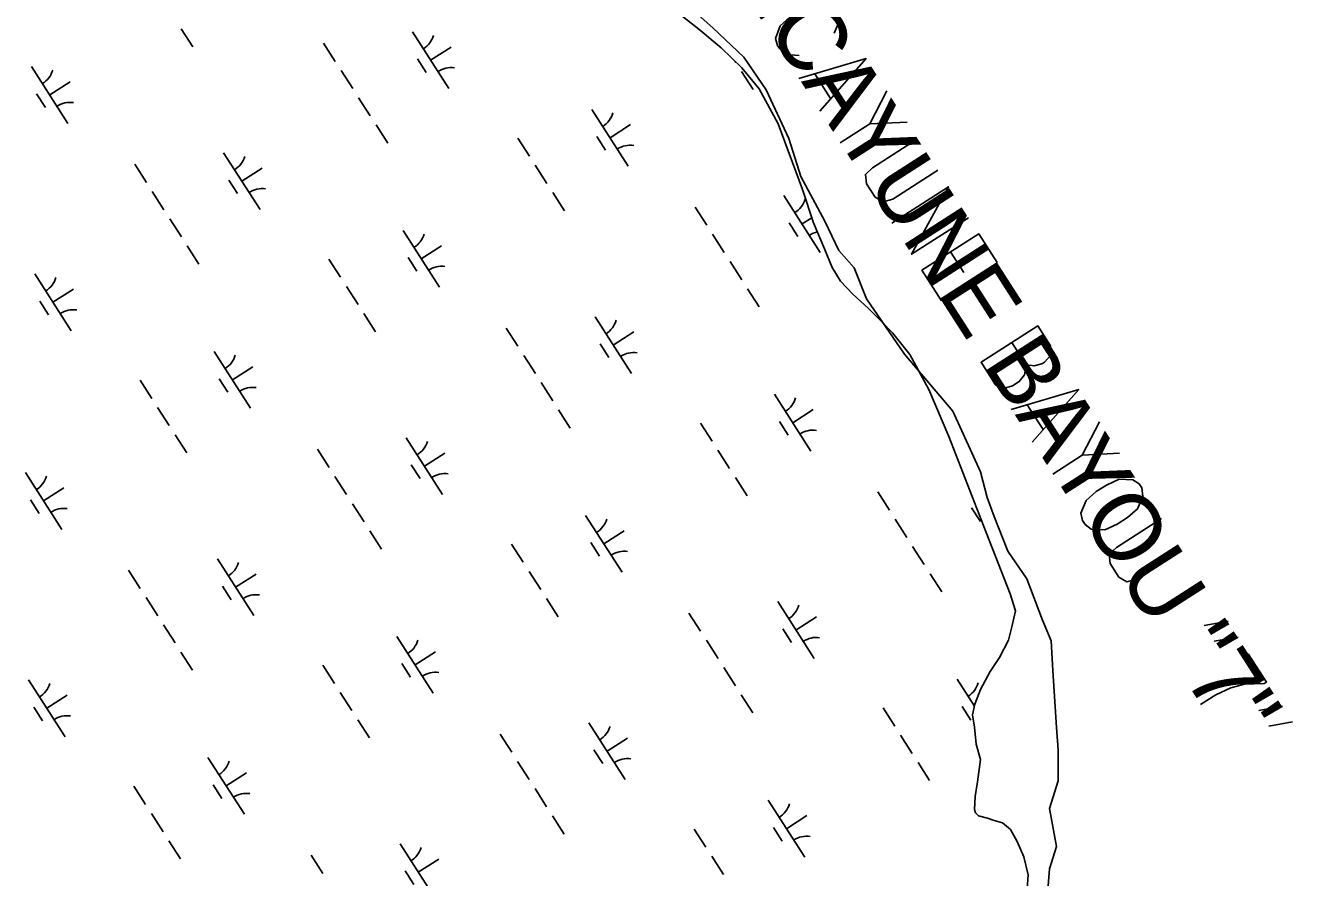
# Model space of a CAD drawing. Extents: x 3962991 to 3983549, y 181631 to 204078.
# Drawn here: x 3968183 to 3969123, y 196968 to 197600 of the extents above; entities that cross this region are included whole.
import ezdxf

# ---------------------------------------------------------------- set-up
doc = ezdxf.new("R2010")
doc.units = 0
for name, color, linetype in [('V-ANNO-MASK', 7, 'Continuous'), ('V-ANNO-MASK2', 7, 'Continuous'), ('V-CHAN-NAID', 7, 'Continuous'), ('V-RIVR-EDGE', 7, 'Continuous'), ('V-WETL-SWMP', 7, 'Continuous')]:
    doc.layers.add(name, color=color, linetype=linetype)

msp = doc.modelspace()

# ---------------------------------------------------------------- linework, layer by layer
at = {"layer": 'V-ANNO-MASK2'}
for p, q in [((3968780.21, 197545.37), (3968768.41, 197563.74)), ((3968809.17, 197526.5), (3968787.3, 197512.46)), ((3968869.15, 197431.61), (3968878.88, 197416.45)), ((3968937.81, 197299.89), (3968926.02, 197318.26)), ((3968966.77, 197281.02), (3968944.91, 197266.98)), ((3969057.26, 197154.66), (3969074.91, 197157.77)), ((3969064.74, 197143), (3969082.4, 197146.11)), ((3969097.69, 197091.69), (3969115.35, 197094.79)), ((3969105.18, 197080.03), (3969122.83, 197083.13))]:
    msp.add_line(p, q, dxfattribs=at)
for points in [[(3968782.72, 197593.92), (3968786.68, 197603.05), (3968785.01, 197608.57), (3968782.95, 197611.77), (3968778.82, 197615.29), (3968768.68, 197615.78), (3968758.66, 197610.99), (3968753.69, 197607.8), (3968750.37, 197605.68), (3968747.58, 197603.47), (3968742.84, 197599.19), (3968739.4, 197589.98), (3968740.88, 197584.76), (3968742.56, 197582.13), (3968747.07, 197578.03), (3968756.88, 197577.33)], [(3968756.6, 197560.27), (3968806.54, 197575.04), (3968772.14, 197536.07)], [(3968821.89, 197551.13), (3968809.17, 197526.5), (3968836.86, 197527.81)], [(3968844.72, 197515.56), (3968811.26, 197494.08), (3968806.05, 197489.09), (3968806.77, 197482.14), (3968813.13, 197472.22), (3968819.15, 197468.68), (3968826.24, 197470.76), (3968859.7, 197492.24)], [(3968825.49, 197452.98), (3968867.56, 197480), (3968840.27, 197429.95), (3968882.35, 197456.97)], [(3968903.69, 197423.73), (3968890.02, 197445.01), (3968847.95, 197418), (3968862.55, 197395.26)], [(3968925.28, 197347.84), (3968931.31, 197347.18), (3968937.22, 197348.92), (3968938.87, 197349.98), (3968943.57, 197355.05), (3968943.37, 197361.92), (3968933.82, 197376.79), (3968891.75, 197349.78), (3968902.42, 197333.16), (3968908.39, 197330.41), (3968915.15, 197332.28), (3968920.12, 197335.47), (3968923.96, 197340.41), (3968925.28, 197347.84), (3968914.61, 197364.45)], [(3968914.21, 197314.79), (3968964.15, 197329.56), (3968929.75, 197290.6)], [(3968979.49, 197305.66), (3968966.77, 197281.02), (3968994.47, 197282.33)], [(3969009.07, 197259.59), (3969010.94, 197256.68), (3969011.8, 197250.23), (3969007.84, 197241.1), (3969000.31, 197234.62), (3968992.69, 197229.73), (3968983.66, 197225.57), (3968973.52, 197226.06), (3968968.87, 197229.66), (3968966.99, 197232.58), (3968965.84, 197238.02), (3968969.62, 197247.44), (3968977.15, 197253.92), (3968984.77, 197258.82), (3968994.13, 197263.18), (3969004.27, 197262.69), (3969009.07, 197259.59)], [(3969025.54, 197233.94), (3968992.08, 197212.45), (3968986.87, 197207.46), (3968987.58, 197200.51), (3968993.95, 197190.6), (3968999.97, 197187.05), (3969007.06, 197189.13), (3969040.52, 197210.61)], [(3969089.93, 197133.65), (3969103.41, 197112.66), (3969101.75, 197111.59), (3969087.03, 197111.2), (3969077.07, 197108.51), (3969065.86, 197103.37), (3969054.6, 197096.14)]]:
    msp.add_lwpolyline(points, dxfattribs=at)
at = {"layer": 'V-RIVR-EDGE'}
msp.add_lwpolyline([(3968670.98, 197617.02), (3968692.76, 197597.81), (3968715.81, 197576.04), (3968732.46, 197551.71), (3968749.1, 197515.85), (3968758.07, 197487.67), (3968776, 197454.38), (3968786.24, 197432.61), (3968797.77, 197419.8), (3968806.73, 197396.75), (3968834.91, 197355.77), (3968870.76, 197313.51), (3968878.45, 197296.86), (3968891.25, 197268.69), (3968896.38, 197249.48), (3968901.5, 197235.39), (3968911.74, 197209.78), (3968925.83, 197189.29), (3968937.36, 197158.55), (3968943.76, 197143.18), (3968945.04, 197121.41), (3968947.6, 197079.15), (3968948.88, 197062.5), (3968948.88, 197039.45), (3968942.48, 197018.96), (3968947.6, 196990.79), (3968942.48, 196974.14), (3968939.92, 196939.56)], dxfattribs=at)
at = {"layer": 'V-WETL-SWMP'}
for p, q in [((3968664.23, 197611.02), (3968682.53, 197596.72)), ((3968298.66, 197597.13), (3968307.29, 197583.66)), ((3968470.1, 197594.89), (3968497.09, 197552.79)), ((3968682.53, 197596.72), (3968699.01, 197583.01)), ((3968404.22, 197586.41), (3968412.86, 197572.94)), ((3968473.86, 197574.73), (3968480.34, 197564.63)), ((3968483.6, 197573.84), (3968498.75, 197583.56)), ((3968699.01, 197583.01), (3968714.29, 197568.08)), ((3968187.62, 197569.06), (3968214.61, 197526.97)), ((3968417.18, 197566.21), (3968425.81, 197552.74)), ((3968709.36, 197572.89), (3968709.84, 197572.15)), ((3968714.16, 197565.41), (3968722.8, 197551.94)), ((3968714.29, 197568.08), (3968727.16, 197552.52)), ((3968201.12, 197548.02), (3968216.27, 197557.73)), ((3968191.38, 197548.9), (3968197.86, 197538.8)), ((3968430.13, 197546), (3968438.76, 197532.53)), ((3968727.16, 197552.52), (3968741.37, 197526.69)), ((3968603.13, 197537.34), (3968630.11, 197495.25)), ((3968443.08, 197525.8), (3968451.72, 197512.33)), ((3968616.62, 197516.3), (3968631.77, 197526.01)), ((3968741.37, 197526.69), (3968759.46, 197477.95)), ((3968548.22, 197516.05), (3968556.86, 197502.58)), ((3968606.89, 197517.19), (3968613.36, 197507.08)), ((3968330.07, 197505.11), (3968357.06, 197463.02)), ((3968264.19, 197496.64), (3968272.83, 197483.17)), ((3968343.56, 197484.07), (3968358.72, 197493.78)), ((3968561.18, 197495.84), (3968569.81, 197482.37)), ((3968333.83, 197484.95), (3968340.31, 197474.85)), ((3968277.14, 197476.43), (3968285.78, 197462.96)), ((3968574.13, 197475.64), (3968582.76, 197462.17)), ((3968745.58, 197473.39), (3968772.56, 197431.3)), ((3968759.46, 197477.95), (3968767.61, 197453.26)), ((3968679.7, 197464.92), (3968688.33, 197451.45)), ((3968290.1, 197456.23), (3968298.73, 197442.76)), ((3968749.34, 197453.23), (3968755.81, 197443.13)), ((3968759.07, 197452.35), (3968766.37, 197457.02)), ((3968767.61, 197453.26), (3968775.69, 197434.02)), ((3968463.1, 197447.57), (3968490.08, 197405.48)), ((3968692.65, 197444.72), (3968701.28, 197431.25)), ((3968303.05, 197436.03), (3968311.69, 197422.56)), ((3968476.59, 197426.53), (3968491.74, 197436.24)), ((3968775.69, 197434.02), (3968781.29, 197420.18)), ((3968408.19, 197426.27), (3968416.83, 197412.81)), ((3968466.86, 197427.41), (3968473.33, 197417.31)), ((3968705.6, 197424.51), (3968714.24, 197411.04)), ((3968190.04, 197415.34), (3968217.03, 197373.25)), ((3968781.29, 197420.18), (3968787.45, 197409.98)), ((3968421.14, 197406.07), (3968429.78, 197392.6)), ((3968787.45, 197409.98), (3968796.63, 197400.41)), ((3968203.53, 197394.29), (3968218.69, 197404.01)), ((3968718.56, 197404.31), (3968727.19, 197390.84)), ((3968796.63, 197400.41), (3968808.24, 197389.67)), ((3968193.8, 197395.18), (3968200.28, 197385.08)), ((3968808.24, 197389.67), (3968818.02, 197380.11)), ((3968434.1, 197385.87), (3968442.73, 197372.4)), ((3968605.55, 197383.62), (3968632.53, 197341.53)), ((3968818.02, 197380.11), (3968825.98, 197371.74)), ((3968539.66, 197375.15), (3968548.3, 197361.68)), ((3968619.04, 197362.57), (3968634.19, 197372.29)), ((3968825.98, 197371.74), (3968838.85, 197355.57)), ((3968609.3, 197363.46), (3968615.78, 197353.36)), ((3968323.06, 197357.8), (3968350.05, 197315.71)), ((3968552.62, 197354.94), (3968561.25, 197341.47)), ((3968838.85, 197355.57), (3968853.06, 197329.75)), ((3968336.56, 197336.75), (3968351.71, 197346.47)), ((3968268.16, 197336.5), (3968276.79, 197323.03)), ((3968326.82, 197337.64), (3968333.3, 197327.54)), ((3968565.57, 197334.74), (3968574.21, 197321.27)), ((3968738.57, 197326.08), (3968765.56, 197283.99)), ((3968853.06, 197329.75), (3968867.97, 197294.87)), ((3968281.11, 197316.3), (3968289.75, 197302.83)), ((3968578.52, 197314.53), (3968587.16, 197301.06)), ((3968752.06, 197305.03), (3968767.22, 197314.75)), ((3968683.66, 197304.78), (3968692.3, 197291.31)), ((3968742.33, 197305.92), (3968748.81, 197295.82)), ((3968294.07, 197296.09), (3968302.7, 197282.62)), ((3968465.51, 197293.85), (3968492.5, 197251.75)), ((3968867.97, 197294.87), (3968895.46, 197223.71)), ((3968399.63, 197285.37), (3968408.27, 197271.9)), ((3968696.62, 197284.58), (3968705.25, 197271.11)), ((3968469.27, 197273.69), (3968475.75, 197263.59)), ((3968479.01, 197272.8), (3968494.16, 197282.52)), ((3968183.03, 197268.02), (3968210.02, 197225.93)), ((3968412.59, 197265.17), (3968421.22, 197251.7)), ((3968709.57, 197264.37), (3968718.21, 197250.9)), ((3968196.53, 197246.98), (3968211.68, 197256.69)), ((3968186.79, 197247.87), (3968193.27, 197237.76)), ((3968815.14, 197253.65), (3968823.77, 197240.18)), ((3968425.54, 197244.96), (3968434.17, 197231.49)), ((3968598.54, 197236.31), (3968625.52, 197194.21)), ((3968884.78, 197241.97), (3968891.25, 197231.87)), ((3968828.09, 197233.45), (3968836.73, 197219.98)), ((3968438.49, 197224.76), (3968447.13, 197211.29)), ((3968612.03, 197215.26), (3968627.18, 197224.97)), ((3968895.46, 197223.71), (3968913.45, 197178.14)), ((3968543.63, 197215.01), (3968552.27, 197201.54)), ((3968602.3, 197216.15), (3968608.77, 197206.04)), ((3968841.04, 197213.24), (3968849.68, 197199.77)), ((3968325.48, 197204.07), (3968352.47, 197161.98)), ((3968259.6, 197195.6), (3968268.24, 197182.13)), ((3968338.97, 197183.03), (3968354.13, 197192.74)), ((3968556.59, 197194.8), (3968565.22, 197181.33)), ((3968854, 197193.04), (3968862.63, 197179.57)), ((3968329.24, 197183.91), (3968335.72, 197173.81)), ((3968272.55, 197175.39), (3968281.19, 197161.93)), ((3968569.54, 197174.6), (3968578.17, 197161.13)), ((3968740.99, 197172.35), (3968767.97, 197130.26)), ((3968913.45, 197178.14), (3968917.23, 197165.5)), ((3968675.11, 197163.88), (3968683.74, 197150.41)), ((3968754.48, 197151.31), (3968769.63, 197161.02)), ((3968917.23, 197165.5), (3968914.93, 197154.59)), ((3968285.51, 197155.19), (3968294.14, 197141.72)), ((3968744.75, 197152.19), (3968751.22, 197142.09)), ((3968914.93, 197154.59), (3968912.04, 197143.68)), ((3968458.51, 197146.53), (3968485.49, 197104.44)), ((3968688.06, 197143.68), (3968696.69, 197130.21)), ((3968912.04, 197143.68), (3968905.54, 197130.91)), ((3968298.46, 197134.99), (3968307.1, 197121.52)), ((3968472, 197125.49), (3968487.15, 197135.2)), ((3968403.6, 197125.23), (3968412.24, 197111.77)), ((3968462.27, 197126.37), (3968468.74, 197116.27)), ((3968701.01, 197123.47), (3968709.65, 197110)), ((3968905.54, 197130.91), (3968898.41, 197120.55)), ((3968185.45, 197114.3), (3968212.44, 197072.21)), ((3968874.01, 197114.81), (3968886.88, 197094.74)), ((3968898.41, 197120.55), (3968891.31, 197107.17)), ((3968416.55, 197105.03), (3968425.19, 197091.56)), ((3968891.31, 197107.17), (3968887.21, 197096.24)), ((3968198.94, 197093.25), (3968214.1, 197102.97)), ((3968713.97, 197103.27), (3968722.6, 197089.8)), ((3968887.21, 197096.24), (3968885.49, 197088.37)), ((3968189.21, 197094.14), (3968195.69, 197084.04)), ((3968819.11, 197093.52), (3968827.74, 197080.05)), ((3968877.77, 197094.65), (3968884.25, 197084.55)), ((3968885.49, 197088.37), (3968886.8, 197079.32)), ((3968429.51, 197084.83), (3968438.14, 197071.36)), ((3968600.96, 197082.58), (3968627.94, 197040.49)), ((3968886.8, 197079.32), (3968888.16, 197066.64)), ((3968535.07, 197074.11), (3968543.71, 197060.64)), ((3968614.45, 197061.53), (3968629.6, 197071.25)), ((3968832.06, 197073.31), (3968840.69, 197059.84)), ((3968604.71, 197062.42), (3968611.19, 197052.32)), ((3968888.16, 197066.64), (3968891.31, 197055.19)), ((3968318.47, 197056.76), (3968345.46, 197014.67)), ((3968548.03, 197053.9), (3968556.66, 197040.43)), ((3968845.01, 197053.11), (3968853.65, 197039.64)), ((3968891.31, 197055.19), (3968889.08, 197038.85)), ((3968331.97, 197035.71), (3968347.12, 197045.43)), ((3968889.08, 197038.85), (3968887.4, 197027.95)), ((3968263.57, 197035.46), (3968272.2, 197021.99)), ((3968322.23, 197036.6), (3968328.71, 197026.5)), ((3968560.98, 197033.7), (3968569.62, 197020.23)), ((3968733.98, 197025.04), (3968760.96, 196982.95)), ((3968887.4, 197027.95), (3968886.91, 197018.27)), ((3968276.52, 197015.26), (3968285.16, 197001.79)), ((3968573.93, 197013.49), (3968582.57, 197000.02)), ((3968747.47, 197003.99), (3968762.63, 197013.71)), ((3968886.91, 197018.27), (3968887.54, 197015.86)), ((3968887.54, 197015.86), (3968889.98, 197013.47)), ((3968889.98, 197013.47), (3968896.65, 197011.74)), ((3968896.65, 197011.74), (3968901.51, 197009.98)), ((3968679.07, 197003.74), (3968687.71, 196990.27)), ((3968737.74, 197004.88), (3968744.22, 196994.78)), ((3968901.51, 197009.98), (3968907.57, 197008.24)), ((3968907.57, 197008.24), (3968913.67, 197003.47)), ((3968913.67, 197003.47), (3968918.61, 196994.47)), ((3968289.48, 196995.05), (3968298.11, 196981.58)), ((3968460.92, 196992.81), (3968487.91, 196950.71)), ((3968918.61, 196994.47), (3968923.58, 196983.04)), ((3968395.04, 196984.33), (3968403.68, 196970.86)), ((3968692.03, 196983.54), (3968700.66, 196970.07)), ((3968923.58, 196983.04), (3968926.76, 196969.78)), ((3968474.42, 196971.76), (3968489.57, 196981.48)), ((3968464.68, 196972.65), (3968471.16, 196962.55)), ((3968926.76, 196969.78), (3968925.71, 196955.87))]:
    msp.add_line(p, q, dxfattribs=at)
for centre, start, end in [((3968468.89, 197597.22), 301.89187, 343.43553), ((3968186.41, 197571.4), 301.89187, 343.43553), ((3968498.7, 197550.72), 81.89186, 123.43552), ((3968216.22, 197524.89), 81.89186, 123.43552), ((3968601.91, 197539.68), 301.89187, 343.43553), ((3968631.73, 197493.17), 81.89186, 123.43552), ((3968328.86, 197507.45), 301.89187, 343.43553), ((3968358.67, 197460.94), 81.89186, 123.43552), ((3968744.36, 197475.73), 301.89187, 343.43553), ((3968461.88, 197449.91), 301.89187, 343.43553), ((3968774.18, 197429.22), 102.15438, 123.43552), ((3968491.7, 197403.4), 81.89186, 123.43552), ((3968188.83, 197417.67), 301.89187, 343.43553), ((3968218.64, 197371.17), 81.89186, 123.43552), ((3968604.33, 197385.96), 301.89187, 343.43553), ((3968321.85, 197360.13), 301.89187, 343.43553), ((3968634.15, 197339.45), 81.89186, 123.43552), ((3968351.66, 197313.63), 81.89186, 123.43552), ((3968737.35, 197328.41), 301.89187, 343.43553), ((3968767.17, 197281.91), 81.89186, 123.43552), ((3968464.3, 197296.18), 301.89187, 343.43553), ((3968181.82, 197270.36), 301.89187, 343.43553), ((3968494.11, 197249.68), 81.89186, 123.43552), ((3968211.63, 197223.85), 81.89186, 123.43552), ((3968597.32, 197238.64), 301.89187, 343.43553), ((3968627.14, 197192.13), 81.89186, 123.43552), ((3968324.27, 197206.41), 301.89187, 343.43553), ((3968354.08, 197159.9), 81.89186, 123.43552), ((3968739.77, 197174.69), 301.89187, 343.43553), ((3968457.29, 197148.87), 301.89187, 343.43553), ((3968769.59, 197128.18), 81.89186, 123.43552), ((3968487.11, 197102.36), 81.89186, 123.43552), ((3968184.24, 197116.64), 301.89187, 343.43553), ((3968872.8, 197117.15), 301.89187, 343.43553), ((3968214.05, 197070.13), 81.89186, 123.43552), ((3968599.74, 197084.92), 301.89187, 343.43553), ((3968317.26, 197059.09), 301.89187, 343.43553), ((3968629.56, 197038.41), 81.89186, 123.43552), ((3968347.07, 197012.59), 81.89186, 123.43552), ((3968732.76, 197027.37), 301.89187, 343.43553), ((3968762.58, 196980.87), 81.89186, 123.43552), ((3968459.71, 196995.14), 301.89187, 343.43553)]:
    msp.add_arc(centre, 17.62, start, end, dxfattribs=at)

# ---------------------------------------------------------------- texts
at = {"layer": 'V-ANNO-MASK'}
msp.add_text('PICAYUNE BAYOU "7"', height=50, rotation=302.70241, dxfattribs=at).set_placement((3968697.83, 197651.81))
at = {"layer": 'V-CHAN-NAID'}
msp.add_text('PICAYUNE BAYOU "7"', height=50, rotation=302.70241, dxfattribs=at).set_placement((3968697.83, 197651.81))

doc.saveas('drawing.dxf')
